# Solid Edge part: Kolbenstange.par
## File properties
Username: bmolnar
Dokumentum tartalom típus: 0
Author: bmolnar
Last saved by: bmolnar
Revision: 96
Sűrűség: 0,000 kg/m^3
Pontosság: 0,990
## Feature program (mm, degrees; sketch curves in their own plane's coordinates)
base feature "unnamed BaseFeature 1"
sketch for "unnamed Protrusion 1" plane through (62.5, 0, 0) normal (1, 0, 0) x-axis (0, 0, -1)
  circle centre (0, 0) radius 50
extrude "unnamed Protrusion 1" add finite 14 along +normal
thread "unnamed Thread 1"
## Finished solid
Body 1: solid body, 17 faces, 23 edges, 8 vertices.
  Faces by surface: plane 8, cylinder 4, torus 3, cone 2
  Edges by curve: circle 13, line 6, ellipse 2, intersection 2
Bounding box of the edges (mm; curved faces can reach further): 391.500 x 100.000 x 100.000, from (-315, -50, -50) to (76.5, 50, 50).
Cylindrical faces by radius (mm): R7 x1, R8 x1, R12.5 x1, R50 x1
Conical faces (half-angle, radius in mm at the cone's reference point): 20 deg R7.4 x1, 60 deg R7.6 x1
Toroidal faces (ring radius, tube radius in mm): R7.4 r0.4 x2, R10.7 r1.8 x1
Planar faces by outward normal: +x 1, +z 1, -x 3, -z 1, oblique 2
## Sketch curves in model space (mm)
circle centre (62.5, 0, 0) radius 50
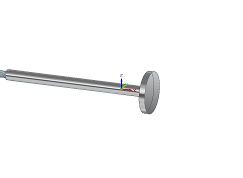
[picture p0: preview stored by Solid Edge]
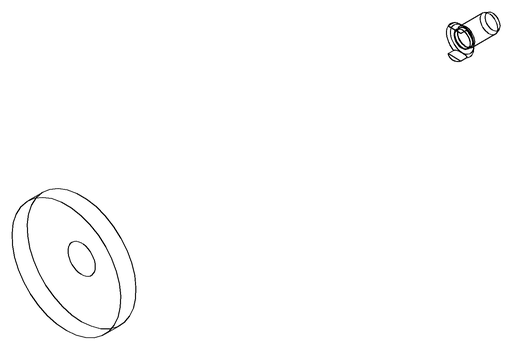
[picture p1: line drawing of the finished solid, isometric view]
